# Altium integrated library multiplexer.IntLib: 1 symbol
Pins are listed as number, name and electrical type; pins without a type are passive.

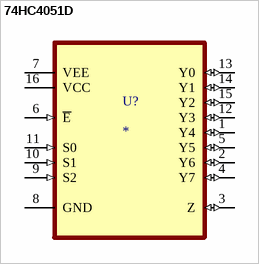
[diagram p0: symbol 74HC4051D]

## 74HC4051D
designator U?
1 Circuit IC Switch 8:1 130Ohm 16-SOIC; MP: 74HC4051D; MF: Toshiba
footprint SOIC127P600X175-16N
pins: 1 Y4 (io), 2 Y6 (io), 3 Z (io), 4 Y7 (io), 5 Y5 (io), 6 ~{E} (in), 7 VEE (power), 8 GND, 9 S2 (in), 10 S1 (in), 11 S0 (in), 12 Y3 (io), 13 Y0 (io), 14 Y1 (io), 15 Y2 (io), 16 VCC (power)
